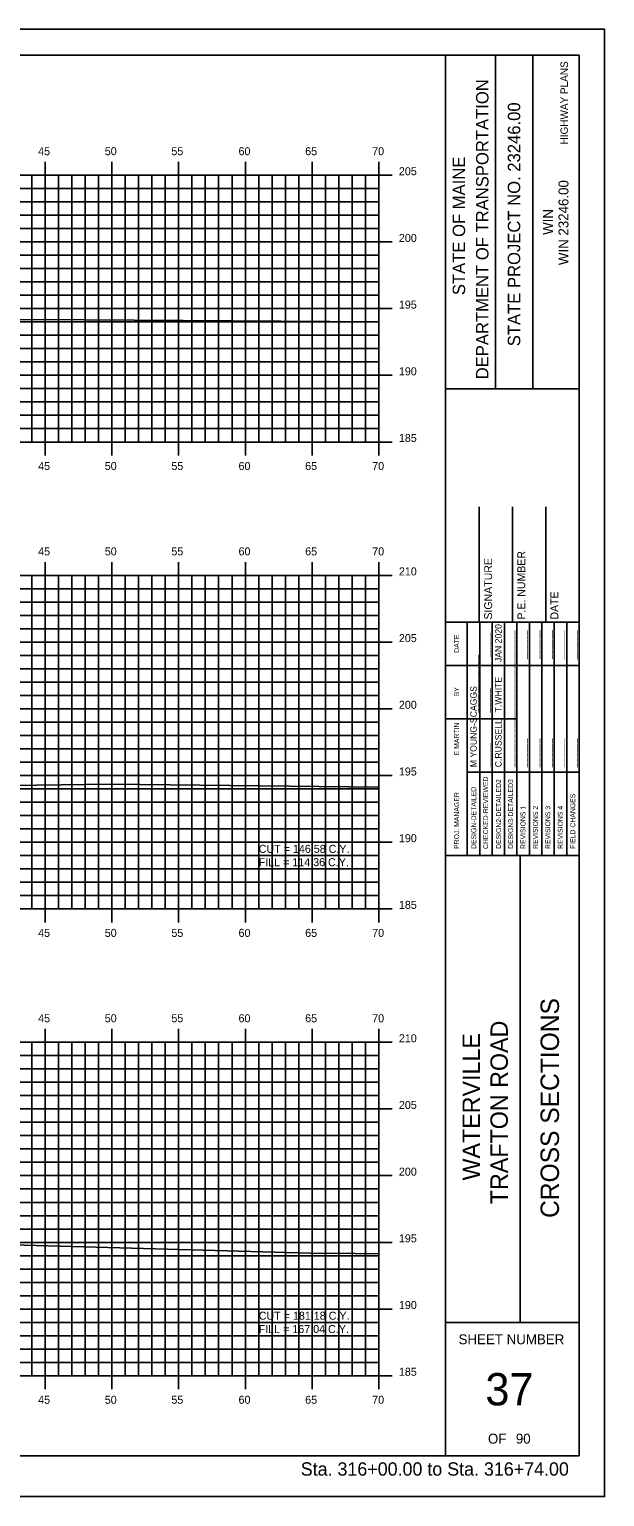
# Model space of a CAD drawing. Extents: x 1138763 to 1138933, y 608981 to 609091.
# Drawn here: x 1138890 to 1138933.1, y 608981.3 to 609091.3 of the extents above; entities that cross this region are included whole.
import ezdxf

# ---------------------------------------------------------------- set-up
doc = ezdxf.new("R2010")
doc.units = 0
for name, color, linetype in [('BORDER', 7, 'Continuous'), ('D_Text_Standard', 7, 'Continuous'), ('H_V ANNOTATION', 7, 'Continuous'), ('HIGHWAY_TITLE', 7, 'Continuous'), ('MAJOR', 7, 'Continuous'), ('MINOR', 7, 'Continuous'), ('PLOT BOUNDARY', 7, 'Continuous'), ('S_Roadway_Centerline', 7, 'Continuous')]:
    doc.layers.add(name, color=color, linetype=linetype)

msp = doc.modelspace()

# ---------------------------------------------------------------- linework, layer by layer
at = {"layer": 'BORDER'}
for p, q in [((1138921.19, 608984.34), (1138921.19, 609089.34)), ((1138924.92, 609064.33), (1138924.92, 609089.33)), ((1138927.72, 609064.33), (1138927.72, 609089.33)), ((1138921.19, 609064.33), (1138931.19, 609064.33)), ((1138923.69, 609046.84), (1138923.69, 609055.49)), ((1138926.19, 609046.84), (1138926.19, 609055.49)), ((1138928.69, 609046.84), (1138928.69, 609055.49)), ((1138921.19, 609046.84), (1138931.19, 609046.84)), ((1138921.19, 609029.34), (1138931.19, 609029.34)), ((1138926.78, 608994.34), (1138926.78, 609029.34)), ((1138921.19, 608994.34), (1138931.19, 608994.34))]:
    msp.add_line(p, q, dxfattribs=at)
msp.add_lwpolyline([(1138771.19, 608984.34), (1138931.19, 608984.34), (1138931.19, 609089.34), (1138771.19, 609089.34)], close=True, dxfattribs=at)
for points in [[(1138922.81, 609043.59), (1138922.81, 609046.84)], [(1138922.81, 609029.34), (1138922.81, 609046.13)], [(1138923.74, 609029.34), (1138923.74, 609046.84)], [(1138924.67, 609046.84), (1138924.67, 609029.34)], [(1138925.6, 609029.34), (1138925.6, 609046.84)], [(1138926.53, 609029.34), (1138926.53, 609046.84)], [(1138927.47, 609029.34), (1138927.47, 609046.84)], [(1138928.4, 609029.34), (1138928.4, 609046.84)], [(1138929.33, 609029.34), (1138929.33, 609046.84)], [(1138930.26, 609029.34), (1138930.26, 609046.84)], [(1138921.19, 609043.59), (1138931.19, 609043.59)], [(1138921.19, 609039.59), (1138922.81, 609039.59)], [(1138922.81, 609039.59), (1138926.53, 609039.59)], [(1138922.81, 609035.59), (1138931.19, 609035.59)]]:
    msp.add_lwpolyline(points, dxfattribs=at)
at = {"layer": 'MAJOR'}
for p, q in [((1138891.19, 609081.34), (1138891.19, 609080.34)), ((1138896.19, 609081.34), (1138896.19, 609080.34)), ((1138901.19, 609081.34), (1138901.19, 609080.34)), ((1138906.19, 609081.34), (1138906.19, 609080.34)), ((1138911.19, 609081.34), (1138911.19, 609080.34)), ((1138916.19, 609081.34), (1138916.19, 609080.34)), ((1138776.19, 609080.34), (1138916.19, 609080.34)), ((1138776.19, 609080.34), (1138916.19, 609080.34)), ((1138891.19, 609060.34), (1138891.19, 609080.34)), ((1138896.19, 609060.34), (1138896.19, 609080.34)), ((1138901.19, 609060.34), (1138901.19, 609080.34)), ((1138906.19, 609060.34), (1138906.19, 609080.34)), ((1138911.19, 609060.34), (1138911.19, 609080.34)), ((1138917.19, 609080.34), (1138915.19, 609080.34)), ((1138916.19, 609060.34), (1138916.19, 609080.34)), ((1138916.19, 609060.34), (1138916.19, 609080.34)), ((1138776.19, 609075.34), (1138916.19, 609075.34)), ((1138917.19, 609075.34), (1138915.19, 609075.34)), ((1138776.19, 609070.34), (1138916.19, 609070.34)), ((1138917.19, 609070.34), (1138915.19, 609070.34)), ((1138776.19, 609065.34), (1138916.19, 609065.34)), ((1138917.19, 609065.34), (1138915.19, 609065.34)), ((1138776.19, 609060.34), (1138916.19, 609060.34)), ((1138776.19, 609060.34), (1138916.19, 609060.34)), ((1138891.19, 609059.33), (1138891.19, 609060.34)), ((1138896.19, 609059.33), (1138896.19, 609060.34)), ((1138901.19, 609059.33), (1138901.19, 609060.34)), ((1138906.19, 609059.33), (1138906.19, 609060.34)), ((1138911.19, 609059.33), (1138911.19, 609060.34)), ((1138917.19, 609060.34), (1138915.19, 609060.34)), ((1138916.19, 609059.33), (1138916.19, 609060.34)), ((1138891.19, 609051.34), (1138891.19, 609050.34)), ((1138896.19, 609051.34), (1138896.19, 609050.34)), ((1138901.19, 609051.34), (1138901.19, 609050.34)), ((1138906.19, 609051.34), (1138906.19, 609050.34)), ((1138911.19, 609051.34), (1138911.19, 609050.34)), ((1138916.19, 609051.34), (1138916.19, 609050.34)), ((1138776.19, 609050.34), (1138916.19, 609050.34)), ((1138776.19, 609050.34), (1138916.19, 609050.34)), ((1138891.19, 609025.34), (1138891.19, 609050.34)), ((1138896.19, 609025.34), (1138896.19, 609050.34)), ((1138901.19, 609025.34), (1138901.19, 609050.34)), ((1138906.19, 609025.34), (1138906.19, 609050.34)), ((1138911.19, 609025.34), (1138911.19, 609050.34)), ((1138917.19, 609050.34), (1138915.19, 609050.34)), ((1138916.19, 609025.34), (1138916.19, 609050.34)), ((1138916.19, 609025.34), (1138916.19, 609050.34)), ((1138776.19, 609045.34), (1138916.19, 609045.34)), ((1138917.19, 609045.34), (1138915.19, 609045.34)), ((1138776.19, 609040.34), (1138916.19, 609040.34)), ((1138917.19, 609040.34), (1138915.19, 609040.34)), ((1138776.19, 609035.34), (1138916.19, 609035.34)), ((1138917.19, 609035.34), (1138915.19, 609035.34)), ((1138776.19, 609030.34), (1138916.19, 609030.34)), ((1138917.19, 609030.34), (1138915.19, 609030.34)), ((1138776.19, 609025.34), (1138916.19, 609025.34)), ((1138776.19, 609025.34), (1138916.19, 609025.34)), ((1138891.19, 609024.33), (1138891.19, 609025.34)), ((1138896.19, 609024.33), (1138896.19, 609025.34)), ((1138901.19, 609024.33), (1138901.19, 609025.34)), ((1138906.19, 609024.33), (1138906.19, 609025.34)), ((1138911.19, 609024.33), (1138911.19, 609025.34)), ((1138917.19, 609025.34), (1138915.19, 609025.34)), ((1138916.19, 609024.33), (1138916.19, 609025.34)), ((1138891.19, 609016.34), (1138891.19, 609015.34)), ((1138896.19, 609016.34), (1138896.19, 609015.34)), ((1138901.19, 609016.34), (1138901.19, 609015.34)), ((1138906.19, 609016.34), (1138906.19, 609015.34)), ((1138911.19, 609016.34), (1138911.19, 609015.34)), ((1138916.19, 609016.34), (1138916.19, 609015.34)), ((1138776.19, 609015.34), (1138916.19, 609015.34)), ((1138776.19, 609015.34), (1138916.19, 609015.34)), ((1138891.19, 608990.34), (1138891.19, 609015.34)), ((1138896.19, 608990.34), (1138896.19, 609015.34)), ((1138901.19, 608990.34), (1138901.19, 609015.34)), ((1138906.19, 608990.34), (1138906.19, 609015.34)), ((1138911.19, 608990.34), (1138911.19, 609015.34)), ((1138917.19, 609015.34), (1138915.19, 609015.34)), ((1138916.19, 608990.34), (1138916.19, 609015.34)), ((1138916.19, 608990.34), (1138916.19, 609015.34)), ((1138776.19, 609010.34), (1138916.19, 609010.34)), ((1138917.19, 609010.34), (1138915.19, 609010.34)), ((1138776.19, 609005.34), (1138916.19, 609005.34)), ((1138917.19, 609005.34), (1138915.19, 609005.34)), ((1138776.19, 609000.34), (1138916.19, 609000.34)), ((1138917.19, 609000.34), (1138915.19, 609000.34)), ((1138776.19, 608995.34), (1138916.19, 608995.34)), ((1138917.19, 608995.34), (1138915.19, 608995.34)), ((1138776.19, 608990.34), (1138916.19, 608990.34)), ((1138776.19, 608990.34), (1138916.19, 608990.34)), ((1138891.19, 608989.33), (1138891.19, 608990.34)), ((1138896.19, 608989.33), (1138896.19, 608990.34)), ((1138901.19, 608989.33), (1138901.19, 608990.34)), ((1138906.19, 608989.33), (1138906.19, 608990.34)), ((1138911.19, 608989.33), (1138911.19, 608990.34)), ((1138917.19, 608990.34), (1138915.19, 608990.34)), ((1138916.19, 608989.33), (1138916.19, 608990.34))]:
    msp.add_line(p, q, dxfattribs=at)
at = {"layer": 'MINOR'}
for p, q in [((1138890.19, 609060.34), (1138890.19, 609080.34)), ((1138892.19, 609060.34), (1138892.19, 609080.34)), ((1138893.19, 609060.34), (1138893.19, 609080.34)), ((1138894.19, 609060.34), (1138894.19, 609080.34)), ((1138895.19, 609060.34), (1138895.19, 609080.34)), ((1138897.19, 609060.34), (1138897.19, 609080.34)), ((1138898.19, 609060.34), (1138898.19, 609080.34)), ((1138899.19, 609060.34), (1138899.19, 609080.34)), ((1138900.19, 609060.34), (1138900.19, 609080.34)), ((1138902.19, 609060.34), (1138902.19, 609080.34)), ((1138903.19, 609060.34), (1138903.19, 609080.34)), ((1138904.19, 609060.34), (1138904.19, 609080.34)), ((1138905.19, 609060.34), (1138905.19, 609080.34)), ((1138907.19, 609060.34), (1138907.19, 609080.34)), ((1138908.19, 609060.34), (1138908.19, 609080.34)), ((1138909.19, 609060.34), (1138909.19, 609080.34)), ((1138910.19, 609060.34), (1138910.19, 609080.34)), ((1138912.19, 609060.34), (1138912.19, 609080.34)), ((1138913.19, 609060.34), (1138913.19, 609080.34)), ((1138914.19, 609060.34), (1138914.19, 609080.34)), ((1138915.19, 609060.34), (1138915.19, 609080.34)), ((1138776.19, 609079.34), (1138916.19, 609079.34)), ((1138916.19, 609079.34), (1138915.19, 609079.34)), ((1138776.19, 609078.34), (1138916.19, 609078.34)), ((1138916.19, 609078.34), (1138915.19, 609078.34)), ((1138776.19, 609077.34), (1138916.19, 609077.34)), ((1138916.19, 609077.34), (1138915.19, 609077.34)), ((1138776.19, 609076.34), (1138916.19, 609076.34)), ((1138916.19, 609076.34), (1138915.19, 609076.34)), ((1138776.19, 609074.34), (1138916.19, 609074.34)), ((1138776.19, 609073.34), (1138916.19, 609073.34)), ((1138916.19, 609074.34), (1138915.19, 609074.34)), ((1138916.19, 609073.34), (1138915.19, 609073.34)), ((1138776.19, 609072.34), (1138916.19, 609072.34)), ((1138916.19, 609072.34), (1138915.19, 609072.34)), ((1138776.19, 609071.34), (1138916.19, 609071.34)), ((1138916.19, 609071.34), (1138915.19, 609071.34)), ((1138776.19, 609069.34), (1138916.19, 609069.34)), ((1138916.19, 609069.34), (1138915.19, 609069.34)), ((1138776.19, 609068.34), (1138916.19, 609068.34)), ((1138916.19, 609068.34), (1138915.19, 609068.34)), ((1138776.19, 609067.34), (1138916.19, 609067.34)), ((1138916.19, 609067.34), (1138915.19, 609067.34)), ((1138776.19, 609066.34), (1138916.19, 609066.34)), ((1138916.19, 609066.34), (1138915.19, 609066.34)), ((1138776.19, 609064.34), (1138916.19, 609064.34)), ((1138916.19, 609064.34), (1138915.19, 609064.34)), ((1138776.19, 609063.34), (1138916.19, 609063.34)), ((1138776.19, 609062.34), (1138916.19, 609062.34)), ((1138916.19, 609063.34), (1138915.19, 609063.34)), ((1138916.19, 609062.34), (1138915.19, 609062.34)), ((1138776.19, 609061.34), (1138916.19, 609061.34)), ((1138916.19, 609061.34), (1138915.19, 609061.34)), ((1138890.19, 609025.34), (1138890.19, 609050.34)), ((1138892.19, 609025.34), (1138892.19, 609050.34)), ((1138893.19, 609025.34), (1138893.19, 609050.34)), ((1138894.19, 609025.34), (1138894.19, 609050.34)), ((1138895.19, 609025.34), (1138895.19, 609050.34)), ((1138897.19, 609025.34), (1138897.19, 609050.34)), ((1138898.19, 609025.34), (1138898.19, 609050.34)), ((1138899.19, 609025.34), (1138899.19, 609050.34)), ((1138900.19, 609025.34), (1138900.19, 609050.34)), ((1138902.19, 609025.34), (1138902.19, 609050.34)), ((1138903.19, 609025.34), (1138903.19, 609050.34)), ((1138904.19, 609025.34), (1138904.19, 609050.34)), ((1138905.19, 609025.34), (1138905.19, 609050.34)), ((1138907.19, 609025.34), (1138907.19, 609050.34)), ((1138908.19, 609025.34), (1138908.19, 609050.34)), ((1138909.19, 609025.34), (1138909.19, 609050.34)), ((1138910.19, 609025.34), (1138910.19, 609050.34)), ((1138912.19, 609025.34), (1138912.19, 609050.34)), ((1138913.19, 609025.34), (1138913.19, 609050.34)), ((1138914.19, 609025.34), (1138914.19, 609050.34)), ((1138915.19, 609025.34), (1138915.19, 609050.34)), ((1138776.19, 609049.34), (1138916.19, 609049.34)), ((1138916.19, 609049.34), (1138915.19, 609049.34)), ((1138776.19, 609048.34), (1138916.19, 609048.34)), ((1138916.19, 609048.34), (1138915.19, 609048.34)), ((1138776.19, 609047.34), (1138916.19, 609047.34)), ((1138916.19, 609047.34), (1138915.19, 609047.34)), ((1138776.19, 609046.34), (1138916.19, 609046.34)), ((1138916.19, 609046.34), (1138915.19, 609046.34)), ((1138776.19, 609044.34), (1138916.19, 609044.34)), ((1138916.19, 609044.34), (1138915.19, 609044.34)), ((1138776.19, 609043.34), (1138916.19, 609043.34)), ((1138916.19, 609043.34), (1138915.19, 609043.34)), ((1138776.19, 609042.34), (1138916.19, 609042.34)), ((1138916.19, 609042.34), (1138915.19, 609042.34)), ((1138776.19, 609041.34), (1138916.19, 609041.34)), ((1138916.19, 609041.34), (1138915.19, 609041.34)), ((1138776.19, 609039.34), (1138916.19, 609039.34)), ((1138916.19, 609039.34), (1138915.19, 609039.34)), ((1138776.19, 609038.34), (1138916.19, 609038.34)), ((1138916.19, 609038.34), (1138915.19, 609038.34)), ((1138776.19, 609037.34), (1138916.19, 609037.34)), ((1138916.19, 609037.34), (1138915.19, 609037.34)), ((1138776.19, 609036.34), (1138916.19, 609036.34)), ((1138916.19, 609036.34), (1138915.19, 609036.34)), ((1138776.19, 609034.34), (1138916.19, 609034.34)), ((1138916.19, 609034.34), (1138915.19, 609034.34)), ((1138776.19, 609033.34), (1138916.19, 609033.34)), ((1138916.19, 609033.34), (1138915.19, 609033.34)), ((1138776.19, 609032.34), (1138916.19, 609032.34)), ((1138916.19, 609032.34), (1138915.19, 609032.34)), ((1138776.19, 609031.34), (1138916.19, 609031.34)), ((1138916.19, 609031.34), (1138915.19, 609031.34)), ((1138776.19, 609029.34), (1138916.19, 609029.34)), ((1138916.19, 609029.34), (1138915.19, 609029.34)), ((1138776.19, 609028.34), (1138916.19, 609028.34)), ((1138916.19, 609028.34), (1138915.19, 609028.34)), ((1138776.19, 609027.34), (1138916.19, 609027.34)), ((1138916.19, 609027.34), (1138915.19, 609027.34)), ((1138776.19, 609026.34), (1138916.19, 609026.34)), ((1138916.19, 609026.34), (1138915.19, 609026.34)), ((1138890.19, 608990.34), (1138890.19, 609015.34)), ((1138892.19, 608990.34), (1138892.19, 609015.34)), ((1138893.19, 608990.34), (1138893.19, 609015.34)), ((1138894.19, 608990.34), (1138894.19, 609015.34)), ((1138895.19, 608990.34), (1138895.19, 609015.34)), ((1138897.19, 608990.34), (1138897.19, 609015.34)), ((1138898.19, 608990.34), (1138898.19, 609015.34)), ((1138899.19, 608990.34), (1138899.19, 609015.34)), ((1138900.19, 608990.34), (1138900.19, 609015.34)), ((1138902.19, 608990.34), (1138902.19, 609015.34)), ((1138903.19, 608990.34), (1138903.19, 609015.34)), ((1138904.19, 608990.34), (1138904.19, 609015.34)), ((1138905.19, 608990.34), (1138905.19, 609015.34)), ((1138907.19, 608990.34), (1138907.19, 609015.34)), ((1138908.19, 608990.34), (1138908.19, 609015.34)), ((1138909.19, 608990.34), (1138909.19, 609015.34)), ((1138910.19, 608990.34), (1138910.19, 609015.34)), ((1138912.19, 608990.34), (1138912.19, 609015.34)), ((1138913.19, 608990.34), (1138913.19, 609015.34)), ((1138914.19, 608990.34), (1138914.19, 609015.34)), ((1138915.19, 608990.34), (1138915.19, 609015.34)), ((1138776.19, 609014.34), (1138916.19, 609014.34)), ((1138916.19, 609014.34), (1138915.19, 609014.34)), ((1138776.19, 609013.34), (1138916.19, 609013.34)), ((1138916.19, 609013.34), (1138915.19, 609013.34)), ((1138776.19, 609012.34), (1138916.19, 609012.34)), ((1138916.19, 609012.34), (1138915.19, 609012.34)), ((1138776.19, 609011.34), (1138916.19, 609011.34)), ((1138916.19, 609011.34), (1138915.19, 609011.34)), ((1138776.19, 609009.34), (1138916.19, 609009.34)), ((1138916.19, 609009.34), (1138915.19, 609009.34)), ((1138776.19, 609008.34), (1138916.19, 609008.34)), ((1138776.19, 609007.34), (1138916.19, 609007.34)), ((1138916.19, 609008.34), (1138915.19, 609008.34)), ((1138916.19, 609007.34), (1138915.19, 609007.34)), ((1138776.19, 609006.34), (1138916.19, 609006.34)), ((1138916.19, 609006.34), (1138915.19, 609006.34)), ((1138776.19, 609004.34), (1138916.19, 609004.34)), ((1138916.19, 609004.34), (1138915.19, 609004.34)), ((1138776.19, 609003.34), (1138916.19, 609003.34)), ((1138916.19, 609003.34), (1138915.19, 609003.34)), ((1138776.19, 609002.34), (1138916.19, 609002.34)), ((1138916.19, 609002.34), (1138915.19, 609002.34)), ((1138776.19, 609001.34), (1138916.19, 609001.34)), ((1138916.19, 609001.34), (1138915.19, 609001.34)), ((1138776.19, 608999.34), (1138916.19, 608999.34)), ((1138916.19, 608999.34), (1138915.19, 608999.34)), ((1138776.19, 608998.34), (1138916.19, 608998.34)), ((1138916.19, 608998.34), (1138915.19, 608998.34)), ((1138776.19, 608997.34), (1138916.19, 608997.34)), ((1138776.19, 608996.34), (1138916.19, 608996.34)), ((1138916.19, 608997.34), (1138915.19, 608997.34)), ((1138916.19, 608996.34), (1138915.19, 608996.34)), ((1138776.19, 608994.34), (1138916.19, 608994.34)), ((1138916.19, 608994.34), (1138915.19, 608994.34)), ((1138776.19, 608993.34), (1138916.19, 608993.34)), ((1138916.19, 608993.34), (1138915.19, 608993.34)), ((1138776.19, 608992.34), (1138916.19, 608992.34)), ((1138916.19, 608992.34), (1138915.19, 608992.34)), ((1138776.19, 608991.34), (1138916.19, 608991.34)), ((1138916.19, 608991.34), (1138915.19, 608991.34))]:
    msp.add_line(p, q, dxfattribs=at)
at = {"layer": 'PLOT BOUNDARY'}
msp.add_lwpolyline([(1138763.1, 608981.28), (1138933.1, 608981.28), (1138933.1, 609091.28), (1138763.1, 609091.28)], close=True, dxfattribs=at)
at = {"layer": 'S_Roadway_Centerline'}
for points in [[(1138816.59, 609070.73), (1138822.44, 609072.15), (1138824.22, 609072.74), (1138824.7, 609072.88), (1138825.95, 609072.98), (1138828.35, 609073.13), (1138832.66, 609073.63), (1138832.75, 609073.62), (1138835.18, 609073.58), (1138835.49, 609073.64), (1138836.84, 609073.61), (1138847.55, 609073.53), (1138851.56, 609073.33), (1138858.72, 609072.97), (1138862.73, 609072.22), (1138864.41, 609072.02), (1138876.86, 609069.74), (1138877.41, 609069.48), (1138878.01, 609069.44), (1138878.41, 609069.52), (1138894.19, 609069.49), (1138916.19, 609069.36)], [(1138776.19, 609035.32), (1138777.84, 609035.29), (1138782.11, 609035.2), (1138799.16, 609034.95), (1138807.72, 609034.85), (1138818.49, 609035.51), (1138820.34, 609035.68), (1138822.8, 609036.96), (1138826.16, 609038.19), (1138829.47, 609039.24), (1138833.76, 609039.7), (1138836.1, 609040.06), (1138845.53, 609040.11), (1138847.01, 609040.13), (1138856.26, 609039.8), (1138857.4, 609039.78), (1138858.43, 609039.66), (1138864.89, 609039.14), (1138875.54, 609035.08), (1138876.97, 609034.46), (1138879.45, 609034.46), (1138896.1, 609034.7), (1138916.19, 609034.47)], [(1138776.19, 609000.46), (1138787.53, 609000.48), (1138795.81, 609000.37), (1138801.34, 609000.5), (1138814.58, 609000.67), (1138819.91, 609003.49), (1138824.61, 609005.97), (1138825.62, 609006.37), (1138831.81, 609008.51), (1138835.08, 609008.97), (1138835.82, 609009.14), (1138845.11, 609009.2), (1138846.44, 609009.21), (1138847.93, 609009.18), (1138857.38, 609008.97), (1138857.81, 609008.95), (1138860.36, 609008.82), (1138864.44, 609006.86), (1138878.85, 609000.43), (1138878.89, 609000.44), (1138911.07, 608999.54), (1138914.41, 608999.51), (1138916.19, 608999.49)]]:
    msp.add_lwpolyline(points, dxfattribs=at)

# ---------------------------------------------------------------- texts
at = {"layer": 'BORDER'}
for s, height, p in [('DEPARTMENT OF TRANSPORTATION', 0.9318, (1138924.4, 609065.04)), ('STATE PROJECT NO. 23246.00', 0.9318, (1138926.78, 609067.52)), ('STATE OF MAINE', 0.9318, (1138922.65, 609071.35)), ('WIN 23246.00', 0.7453, (1138930.39, 609073.6)), ('WIN', 0.745, (1138929.23, 609075.87)), ('SIGNATURE', 0.591, (1138924.67, 609047.03)), ('P.E. NUMBER', 0.5906, (1138927.15, 609047.03)), ('DATE', 0.591, (1138929.63, 609047.03)), ('DATE', 0.371, (1138922.2, 609044.54)), ('_____', 0.485, (1138924.41, 609044.24)), ('JAN 2020', 0.485, (1138925.38, 609043.84)), ('______', 0.485, (1138926.27, 609044.06)), ('______', 0.485, (1138927.2, 609044.06)), ('______', 0.485, (1138928.14, 609044.07)), ('______', 0.485, (1138929.07, 609044.07)), ('______', 0.485, (1138930, 609044.04)), ('______', 0.485, (1138930.93, 609044.04)), ('____________', 0.4845, (1138923.52, 609040.07)), ('____________', 0.4845, (1138926.27, 609040.07)), ('T.WHITE', 0.485, (1138925.38, 609040.07)), ('BY', 0.371, (1138922.2, 609041.27)), ('M YOUNG-SCAGGS', 0.4845, (1138923.52, 609035.96)), ('_____', 0.485, (1138924.45, 609040.07)), ('C.RUSSELL', 0.485, (1138925.38, 609035.96)), ('____________', 0.4845, (1138926.27, 609035.96)), ('E MARTIN', 0.373, (1138922.2, 609036.85)), ('______', 0.485, (1138927.2, 609035.96)), ('______', 0.485, (1138928.14, 609035.96)), ('______', 0.485, (1138929.07, 609035.96)), ('______', 0.485, (1138930, 609035.96)), ('______', 0.485, (1138930.93, 609035.96)), ('_____', 0.485, (1138924.41, 609035.96)), ('CHECKED-REVIEWED', 0.3727, (1138924.37, 609029.83)), ('DESIGN2-DETAILED2', 0.3727, (1138925.34, 609029.83)), ('DESIGN3-DETAILED3', 0.3727, (1138926.24, 609029.83)), ('PROJ. MANAGER', 0.3727, (1138922.2, 609029.83)), ('DESIGN-DETAILED', 0.3727, (1138923.48, 609029.83)), ('FIELD CHANGES', 0.3727, (1138930.9, 609029.83)), ('REVISIONS 1', 0.3727, (1138927.17, 609029.83)), ('REVISIONS 2', 0.3727, (1138928.1, 609029.83)), ('REVISIONS 3', 0.3727, (1138929.03, 609029.83)), ('REVISIONS 4', 0.3727, (1138929.96, 609029.83)), ('CROSS SECTIONS', 1.3779, (1138929.68, 609002.17))]:
    msp.add_text(s, height=height, rotation=90, dxfattribs=at).set_placement(p)
for s, height, p in [('SHEET NUMBER', 0.7453, (1138922.16, 608992.7)), ('37', 2.419, (1138924.17, 608988.12)), ('OF', 0.745, (1138924.36, 608985.25)), ('90', 0.745, (1138926.45, 608985.25))]:
    msp.add_text(s, height=height, dxfattribs=at).set_placement(p)
at = {"layer": 'D_Text_Standard'}
for s, p in [('CUT = 146.58 C.Y.', (1138907.19, 609029.54)), ('FILL = 114.36 C.Y.', (1138907.19, 609028.54)), ('CUT = 181.18 C.Y.', (1138907.19, 608994.54)), ('FILL = 167.04 C.Y.', (1138907.19, 608993.54))]:
    msp.add_text(s, height=0.6, dxfattribs=at).set_placement(p)
at = {"layer": 'H_V ANNOTATION'}
for s, height, p in [('45', 0.6, (1138890.67, 609081.84)), ('50', 0.6, (1138895.66, 609081.84)), ('55', 0.6, (1138900.65, 609081.84)), ('60', 0.6, (1138905.68, 609081.84)), ('65', 0.6, (1138910.67, 609081.84)), ('70', 0.6, (1138915.69, 609081.84)), ('205', 0.6, (1138917.69, 609080.34)), ('200', 0.6, (1138917.69, 609075.34)), ('195', 0.6, (1138917.69, 609070.34)), ('190', 0.6, (1138917.69, 609065.34)), ('185', 0.6, (1138917.69, 609060.34)), ('45', 0.6, (1138890.67, 609058.24)), ('50', 0.6, (1138895.66, 609058.24)), ('55', 0.6, (1138900.65, 609058.24)), ('60', 0.6, (1138905.68, 609058.24)), ('65', 0.6, (1138910.67, 609058.24)), ('70', 0.6, (1138915.69, 609058.24)), ('45', 0.6, (1138890.67, 609051.84)), ('50', 0.6, (1138895.66, 609051.84)), ('55', 0.6, (1138900.65, 609051.84)), ('60', 0.6, (1138905.68, 609051.84)), ('65', 0.6, (1138910.67, 609051.84)), ('70', 0.6, (1138915.69, 609051.84)), ('210', 0.6, (1138917.69, 609050.34)), ('205', 0.6, (1138917.69, 609045.34)), ('200', 0.6, (1138917.69, 609040.34)), ('195', 0.6, (1138917.69, 609035.34)), ('190', 0.6, (1138917.69, 609030.34)), ('185', 0.6, (1138917.69, 609025.34)), ('45', 0.6, (1138890.67, 609023.24)), ('50', 0.6, (1138895.66, 609023.24)), ('55', 0.6, (1138900.65, 609023.24)), ('60', 0.6, (1138905.68, 609023.24)), ('65', 0.6, (1138910.67, 609023.24)), ('70', 0.6, (1138915.69, 609023.24)), ('45', 0.6, (1138890.67, 609016.84)), ('50', 0.6, (1138895.66, 609016.84)), ('55', 0.6, (1138900.65, 609016.84)), ('60', 0.6, (1138905.68, 609016.84)), ('65', 0.6, (1138910.67, 609016.84)), ('70', 0.6, (1138915.69, 609016.84)), ('210', 0.6, (1138917.69, 609015.34)), ('205', 0.6, (1138917.69, 609010.34)), ('200', 0.6, (1138917.69, 609005.34)), ('195', 0.6, (1138917.69, 609000.34)), ('190', 0.6, (1138917.69, 608995.34)), ('185', 0.6, (1138917.69, 608990.34)), ('45', 0.6, (1138890.67, 608988.24)), ('50', 0.6, (1138895.66, 608988.24)), ('55', 0.6, (1138900.65, 608988.24)), ('60', 0.6, (1138905.68, 608988.24)), ('65', 0.6, (1138910.67, 608988.24)), ('70', 0.6, (1138915.69, 608988.24)), ('Sta. 316+00.00 to Sta. 316+74.00', 1.0002, (1138910.34, 608982.85))]:
    msp.add_text(s, height=height, dxfattribs=at).set_placement(p)
at = {"layer": 'HIGHWAY_TITLE'}
for s, height, p in [('HIGHWAY PLANS', 0.559, (1138930.35, 609082.65)), ('TRAFTON ROAD', 1.3043, (1138925.85, 609003.2)), ('WATERVILLE', 1.304, (1138923.76, 609004.98))]:
    msp.add_text(s, height=height, rotation=90, dxfattribs=at).set_placement(p)

doc.saveas('drawing.dxf')
